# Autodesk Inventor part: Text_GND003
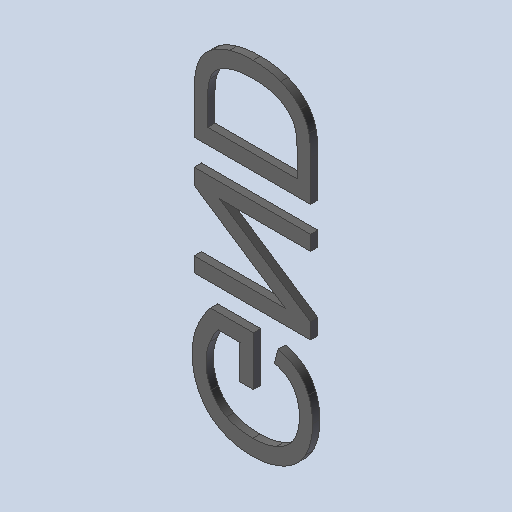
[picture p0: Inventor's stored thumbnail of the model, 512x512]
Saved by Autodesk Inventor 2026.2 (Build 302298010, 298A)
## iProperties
Created: 2026-10
Part Number: Text_GND003
Material: Générique
Document SubType Name: Modeling
Designer: mel
Density: 1 g/cm^3
Appearance: Par défaut
Author: mel
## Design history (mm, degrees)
feature "Base1"
feature "Base2"
feature "Base3"
node "Solide1"
node "Solide2"
node "Solide3"
